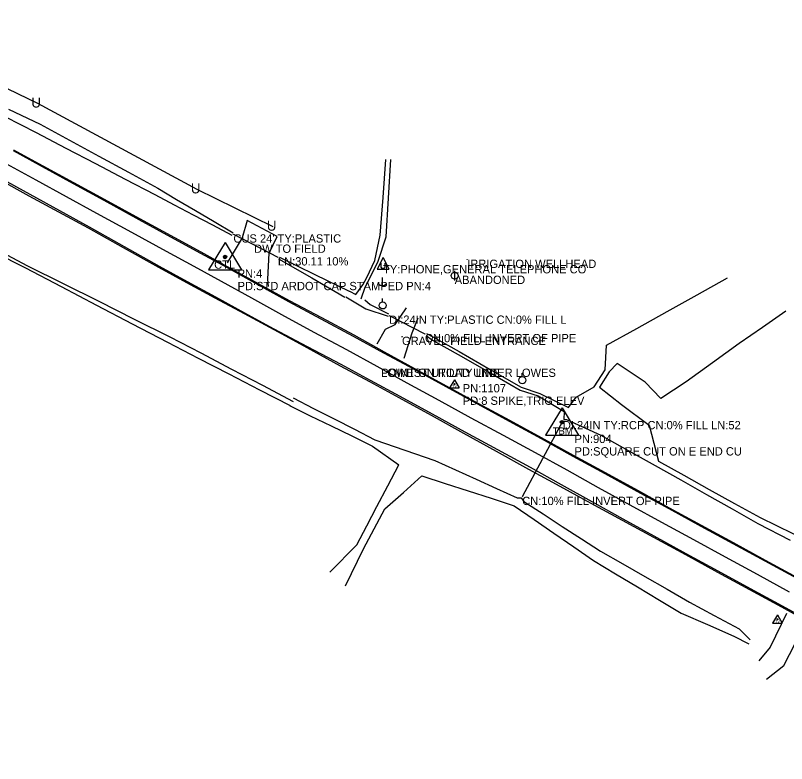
# Model space of a CAD drawing. Extents: x 1411444 to 1458157, y 300965 to 327300.
# Drawn here: x 1455617.6 to 1456081.3, y 301959.3 to 302409.4 of the extents above; entities that cross this region are included whole.
import ezdxf

# ---------------------------------------------------------------- set-up
doc = ezdxf.new("R2010")
doc.units = 0
for name, color, linetype in [('S_CROSS_DRAIN', 7, 'Continuous'), ('S_CROSS_DRAIN_ANNOT', 7, 'Continuous'), ('S_DITCHLINE', 7, 'Continuous'), ('S_DRG_PT_SYM', 7, 'Continuous'), ('S_DRIVEWAY', 7, 'Continuous'), ('S_EDGE_PAVEMENT', 7, 'Continuous'), ('S_ELECTRIC_UTILITIES_ANNOT', 7, 'Continuous'), ('S_MISC_STRUCTURES_ANNOT', 7, 'Continuous'), ('S_MSC_PT_SYM', 7, 'Continuous'), ('S_PAVEMENT_CROWN', 7, 'Continuous'), ('S_PRIMARY_CTL', 7, 'Continuous'), ('S_PRIMARY_CTL_ANNOT', 7, 'Continuous'), ('S_SECONDARY_CTL', 7, 'Continuous'), ('S_SECONDARY_CTL_ANNOT', 7, 'Continuous'), ('S_SHOULDER', 7, 'Continuous'), ('S_SIDE_DRAIN', 7, 'Continuous'), ('S_SIDE_DRAIN_ANNOT', 7, 'Continuous'), ('S_SURVEY_TEXT_ANNOT', 7, 'Continuous'), ('S_UNDERGROUND_CABLE', 7, 'Continuous'), ('S_UTILITY_POLE', 7, 'Continuous'), ('S_UTILITY_POLE_ANNOT', 7, 'Continuous'), ('S_UTL_PT_SYM', 7, 'Continuous')]:
    doc.layers.add(name, color=color, linetype=linetype)

msp = doc.modelspace()

# ---------------------------------------------------------------- linework, layer by layer
at = {"layer": 'S_CROSS_DRAIN'}
for p, q in [((1455748.67, 302277.74), (1455775.41, 302263.98)), ((1455946.75, 302165.41), (1455922.34, 302119.82))]:
    msp.add_line(p, q, dxfattribs=at)
at = {"layer": 'S_DITCHLINE'}
for points in [[(1455613.31, 302353.1), (1455632.46, 302343.94), (1455650.13, 302334.3), (1455667.81, 302324.67), (1455685.48, 302315.03), (1455703.15, 302305.4), (1455714.47, 302298.72), (1455725.79, 302292.05), (1455737.12, 302285.38), (1455748.44, 302278.71)], [(1455611.19, 302348.7), (1455630.11, 302338.98), (1455647.93, 302329.64), (1455665.75, 302320.3), (1455683.57, 302310.96), (1455701.39, 302301.62), (1455712.95, 302295.54), (1455724.51, 302289.45), (1455736.07, 302283.37), (1455747.63, 302277.28)], [(1455822.22, 302241.47), (1455826.43, 302247.25), (1455828.86, 302251.7), (1455833.73, 302262.02), (1455836.98, 302277.13), (1455838.65, 302299.91), (1455840.32, 302322.69)], [(1455825.57, 302238.97), (1455827.89, 302245.84), (1455830.42, 302250.97), (1455835.64, 302261.52), (1455840.6, 302276.21), (1455841.99, 302299.47), (1455843.39, 302322.73)], [(1455604.8, 302266.93), (1455623.63, 302257.6), (1455644.98, 302246.39), (1455666.33, 302235.18), (1455687.68, 302223.96), (1455709.03, 302212.75), (1455727.49, 302203.24), (1455745.95, 302193.73), (1455764.4, 302184.22), (1455782.86, 302174.71)], [(1455606.23, 302268.54), (1455624.82, 302258.77), (1455646.23, 302248.09), (1455667.64, 302237.41), (1455689.05, 302226.72), (1455710.46, 302216.04), (1455729.01, 302206.33), (1455747.56, 302196.61), (1455766.12, 302186.9), (1455784.67, 302177.18)], [(1455775.82, 302263.07), (1455795.76, 302251.46), (1455815.71, 302239.85)], [(1455776.3, 302264.03), (1455797.63, 302253.62), (1455818.28, 302243.54)], [(1455950.15, 302173.46), (1455954.88, 302179.67), (1455965.64, 302185.93), (1455972.18, 302196.15), (1455973, 302210.95), (1455991.2, 302221.08), (1456009.41, 302231.21), (1456027.61, 302241.34), (1456045.82, 302251.46)], [(1455818.38, 302243.51), (1455822.22, 302241.47)], [(1455816.31, 302240.03), (1455828.39, 302232.98), (1455841.69, 302228.51)], [(1455827.76, 302238.3), (1455830.89, 302235.55), (1455842, 302229.89)], [(1456080.85, 302231.48), (1456066.81, 302221.75), (1456052.78, 302212.02), (1456036.82, 302200.48), (1456020.86, 302188.94), (1456005.62, 302178.9), (1455996.36, 302188.75), (1455979.49, 302199.94), (1455974.54, 302195.07), (1455968.85, 302185.66), (1455982.11, 302175.35), (1455998.59, 302162.85), (1456004.29, 302141.21)], [(1455864.67, 302216.87), (1455868.32, 302214.05), (1455883.84, 302205.44), (1455902.44, 302194.74), (1455921.05, 302184.05), (1455931.93, 302180.62), (1455947.6, 302171.05), (1455947.34, 302166.36), (1455949.05, 302166.27), (1455969.67, 302156.8), (1455986.02, 302147.74), (1456002.38, 302138.68), (1456017.8, 302129.95), (1456033.22, 302121.22), (1456048.65, 302112.49), (1456064.07, 302103.76), (1456083.43, 302093.76)], [(1455864.7, 302218.06), (1455868.89, 302215.81), (1455884.5, 302207.22), (1455903.08, 302196.44), (1455921.67, 302185.66), (1455932.91, 302181.95), (1455950.1, 302173.47)], [(1455784.63, 302179.31), (1455796.9, 302173.02), (1455809.17, 302166.72), (1455821.44, 302160.43), (1455833.71, 302154.14), (1455851.72, 302147.93), (1455869.73, 302141.71), (1455882.14, 302136.1), (1455894.55, 302130.49), (1455906.96, 302124.88), (1455919.37, 302119.27), (1455921.7, 302119.11), (1455923.34, 302116.89), (1455934.87, 302109.45), (1455946.39, 302102.01), (1455957.91, 302094.57), (1455969.43, 302087.13), (1455982.8, 302079.46), (1455996.16, 302071.79), (1456009.52, 302064.12), (1456022.88, 302056.45), (1456037.81, 302048.38), (1456052.75, 302040.31), (1456059.49, 302033.64)], [(1455782.34, 302174.69), (1455794.85, 302168.58), (1455807.37, 302162.48), (1455819.88, 302156.38), (1455832.39, 302150.28), (1455848.24, 302139.03)], [(1456004.24, 302141.26), (1456019.52, 302132.77), (1456034.8, 302124.28), (1456050.07, 302115.79), (1456065.35, 302107.3), (1456085.16, 302097.61), (1456104.96, 302087.91), (1456124.76, 302078.22), (1456144.57, 302068.53), (1456162.33, 302059.69), (1456180.09, 302050.85), (1456197.86, 302042.01), (1456215.62, 302033.18), (1456237.44, 302021.54), (1456259.25, 302009.91), (1456281.07, 301998.28), (1456302.88, 301986.64), (1456321.97, 301975.33), (1456341.06, 301964.02), (1456357, 301959.27)], [(1455806.64, 302074.44), (1455822.82, 302090.88), (1455828.88, 302102.41), (1455834.93, 302113.94), (1455841.58, 302126.47), (1455848.23, 302139.01)], [(1455816.03, 302066.14), (1455826.86, 302088.49), (1455833.33, 302100.5), (1455839.79, 302112.52), (1455850.92, 302122.44), (1455862.05, 302132.37)], [(1455862.03, 302132.33), (1455875.91, 302127.85), (1455889.79, 302123.37), (1455903.67, 302118.89), (1455917.55, 302114.41), (1455929.47, 302106.17), (1455941.39, 302097.93), (1455953.31, 302089.69), (1455965.23, 302081.45), (1455978.43, 302073.52), (1455991.63, 302065.58), (1456004.82, 302057.65), (1456018.02, 302049.71), (1456033.82, 302042.87), (1456049.61, 302036.03), (1456058.67, 302031.4)]]:
    msp.add_lwpolyline(points, dxfattribs=at)
at = {"layer": 'S_DRG_PT_SYM'}
for points in [[(1455748.67, 302277.74), (1455748.67, 302277.79), (1455748.67, 302277.74), (1455748.62, 302277.74), (1455748.67, 302277.74), (1455748.67, 302277.69), (1455748.67, 302277.74), (1455748.72, 302277.74)], [(1455775.41, 302263.98), (1455775.41, 302264.03), (1455775.41, 302263.98), (1455775.36, 302263.98), (1455775.41, 302263.98), (1455775.41, 302263.93), (1455775.41, 302263.98), (1455775.46, 302263.98)], [(1455842.3, 302228.87), (1455842.3, 302228.92), (1455842.3, 302228.87), (1455842.25, 302228.87), (1455842.3, 302228.87), (1455842.3, 302228.82), (1455842.3, 302228.87), (1455842.35, 302228.87)], [(1455863.82, 302217.77), (1455863.82, 302217.82), (1455863.82, 302217.77), (1455863.77, 302217.77), (1455863.82, 302217.77), (1455863.82, 302217.72), (1455863.82, 302217.77), (1455863.87, 302217.77)], [(1455946.75, 302165.41), (1455946.75, 302165.46), (1455946.75, 302165.41), (1455946.7, 302165.41), (1455946.75, 302165.41), (1455946.75, 302165.36), (1455946.75, 302165.41), (1455946.8, 302165.41)], [(1455922.34, 302119.82), (1455922.34, 302119.87), (1455922.34, 302119.82), (1455922.29, 302119.82), (1455922.34, 302119.82), (1455922.34, 302119.77), (1455922.34, 302119.82), (1455922.39, 302119.82)]]:
    msp.add_lwpolyline(points, dxfattribs=at)
at = {"layer": 'S_DRIVEWAY'}
for points in [[(1455769.69, 302246.39), (1455769.33, 302250.74), (1455770.17, 302266.43), (1455774.92, 302276.32), (1455756.92, 302285.98), (1455753.97, 302275.69), (1455744.84, 302260.49)], [(1455835.21, 302211.84), (1455840.17, 302220.63), (1455845.87, 302223.56), (1455852.78, 302233.53)], [(1455859.53, 302227.27), (1455855.94, 302218.29), (1455851.21, 302203.01)], [(1456081.28, 302049.64), (1456071.51, 302029.29), (1456064.63, 302021.02)], [(1456069.21, 302009.98), (1456079.73, 302018.24), (1456086.57, 302031.54), (1456101.67, 302034.24)]]:
    msp.add_lwpolyline(points, dxfattribs=at)
at = {"layer": 'S_EDGE_PAVEMENT'}
for points in [[(1455616.19, 302328.12), (1455633.72, 302318.47), (1455652.21, 302308.36), (1455670.71, 302298.26), (1455691.87, 302286.65), (1455713.04, 302275.03), (1455728.95, 302266.41), (1455744.85, 302257.79), (1455763.34, 302247.58), (1455781.83, 302237.37), (1455801.26, 302226.87), (1455820.68, 302216.38), (1455838.98, 302206.48), (1455857.27, 302196.59), (1455876.37, 302186.15), (1455895.47, 302175.71), (1455914.57, 302165.27), (1455933.67, 302154.83), (1455952.88, 302144.29), (1455972.09, 302133.75), (1455991.3, 302123.21), (1456010.51, 302112.67), (1456029.74, 302102.2), (1456048.96, 302091.73), (1456068.18, 302081.25), (1456087.41, 302070.78)], [(1455608.11, 302311.62), (1455626.14, 302301.9), (1455644.02, 302292.07), (1455661.9, 302282.24), (1455682.93, 302270.45), (1455703.95, 302258.66), (1455720.88, 302249.35), (1455737.8, 302240.04), (1455755.4, 302230.45), (1455773, 302220.85), (1455793.1, 302210.18), (1455813.2, 302199.51), (1455830.93, 302189.96), (1455848.65, 302180.41), (1455868.26, 302169.69), (1455887.86, 302158.98), (1455907.46, 302148.26), (1455927.06, 302137.55), (1455945.67, 302127.21), (1455964.28, 302116.88), (1455982.89, 302106.54), (1456001.5, 302096.21), (1456020.78, 302085.71), (1456040.05, 302075.21), (1456059.33, 302064.71), (1456078.61, 302054.21), (1456097.76, 302043.74)]]:
    msp.add_lwpolyline(points, dxfattribs=at)
at = {"layer": 'S_MSC_PT_SYM'}
for points in [[(1455761.09, 302271.59), (1455761.09, 302271.64), (1455761.09, 302271.59), (1455761.04, 302271.59), (1455761.09, 302271.59), (1455761.09, 302271.54), (1455761.09, 302271.59), (1455761.14, 302271.59)], [(1455889.24, 302262.47), (1455889.24, 302262.52), (1455889.24, 302262.47), (1455889.19, 302262.47), (1455889.24, 302262.47), (1455889.24, 302262.42), (1455889.24, 302262.47), (1455889.29, 302262.47)], [(1455850.06, 302216.11), (1455850.06, 302216.16), (1455850.06, 302216.11), (1455850.01, 302216.11), (1455850.06, 302216.11), (1455850.06, 302216.06), (1455850.06, 302216.11), (1455850.11, 302216.11)], [(1455837.47, 302196.93), (1455837.47, 302196.98), (1455837.47, 302196.93), (1455837.42, 302196.93), (1455837.47, 302196.93), (1455837.47, 302196.88), (1455837.47, 302196.93), (1455837.52, 302196.93)]]:
    msp.add_lwpolyline(points, dxfattribs=at)
at = {"layer": 'S_PAVEMENT_CROWN'}
msp.add_lwpolyline([(1455612.22, 302320.13), (1455629.76, 302310.42), (1455648.07, 302300.42), (1455666.38, 302290.42), (1455687.33, 302278.97), (1455708.29, 302267.53), (1455724.83, 302258.58), (1455741.38, 302249.64), (1455759.45, 302239.6), (1455777.52, 302229.56), (1455797.12, 302218.94), (1455816.72, 302208.33), (1455834.84, 302198.32), (1455852.96, 302188.31), (1455872.24, 302177.84), (1455891.52, 302167.38), (1455910.8, 302156.91), (1455930.08, 302146.45), (1455949.08, 302135.97), (1455968.09, 302125.48), (1455987.09, 302115), (1456006.09, 302104.51), (1456025.28, 302094.06), (1456044.46, 302083.61), (1456063.65, 302073.16), (1456082.83, 302062.71)], dxfattribs=at)
at = {"layer": 'S_PRIMARY_CTL'}
for p, q in [((1455743.67, 302272.81), (1455733.63, 302256.29)), ((1455743.67, 302272.81), (1455753.49, 302256.29)), ((1455733.63, 302256.29), (1455753.49, 302256.29)), ((1455946.3, 302173.34), (1455936.26, 302156.83)), ((1455946.3, 302173.34), (1455956.12, 302156.83)), ((1455936.26, 302156.83), (1455956.12, 302156.83))]:
    msp.add_line(p, q, dxfattribs=at)
for centre, radius in [((1455743.67, 302264.11), 1.04), ((1455743.67, 302264.11), 0.609), ((1455743.67, 302264.11), 0.344), ((1455946.3, 302164.64), 1.04), ((1455946.3, 302164.64), 0.609), ((1455946.3, 302164.64), 0.344)]:
    msp.add_circle(centre, radius, dxfattribs=at)
at = {"layer": 'S_SECONDARY_CTL'}
for p, q in [((1455881.56, 302190.23), (1455878.55, 302185.28)), ((1455881.56, 302190.23), (1455884.51, 302185.28)), ((1455878.55, 302185.28), (1455884.51, 302185.28)), ((1456075.81, 302048.71), (1456072.8, 302043.75)), ((1456075.81, 302048.71), (1456078.75, 302043.75)), ((1456072.8, 302043.75), (1456078.75, 302043.75))]:
    msp.add_line(p, q, dxfattribs=at)
for centre, radius in [((1455881.56, 302187.62), 0.311), ((1455881.56, 302187.62), 0.183), ((1455881.56, 302187.62), 0.103), ((1456075.81, 302046.1), 0.311), ((1456075.81, 302046.1), 0.183), ((1456075.81, 302046.1), 0.103)]:
    msp.add_circle(centre, radius, dxfattribs=at)
at = {"layer": 'S_SHOULDER'}
for points in [[(1455616.47, 302328.64), (1455634, 302319.02), (1455652.49, 302308.92), (1455670.98, 302298.83), (1455692.13, 302287.3), (1455713.29, 302275.78), (1455729.13, 302267.1), (1455744.96, 302258.43), (1455763.62, 302248.2), (1455782.29, 302237.97), (1455801.73, 302227.6), (1455821.17, 302217.23), (1455839.37, 302207.09), (1455857.57, 302196.94), (1455876.63, 302186.58), (1455895.69, 302176.22), (1455914.76, 302165.85), (1455933.82, 302155.49), (1455953.07, 302144.93), (1455972.32, 302134.37), (1455991.57, 302123.8), (1456010.81, 302113.24), (1456030.02, 302102.73), (1456049.23, 302092.21), (1456068.45, 302081.7), (1456087.66, 302071.18)], [(1455607.7, 302310.79), (1455625.65, 302300.93), (1455643.52, 302291.24), (1455661.38, 302281.54), (1455682.46, 302269.8), (1455703.54, 302258.05), (1455720.52, 302248.76), (1455737.5, 302239.48), (1455755.19, 302230), (1455772.88, 302220.52), (1455792.83, 302209.57), (1455812.77, 302198.62), (1455830.45, 302189.11), (1455848.13, 302179.6), (1455867.63, 302168.82), (1455887.12, 302158.04), (1455906.62, 302147.26), (1455926.12, 302136.48), (1455944.9, 302126.24), (1455963.69, 302116.01), (1455982.48, 302105.78), (1456001.26, 302095.55), (1456020.53, 302085.04), (1456039.8, 302074.53), (1456059.07, 302064.02), (1456078.33, 302053.51), (1456097.49, 302043.05)]]:
    msp.add_lwpolyline(points, dxfattribs=at)
at = {"layer": 'S_SIDE_DRAIN'}
msp.add_line((1455842.3, 302228.87), (1455863.82, 302217.77), dxfattribs=at)
at = {"layer": 'S_UNDERGROUND_CABLE'}
for p, q in [((1455522.35, 302409.44), (1455630.78, 302356.56)), ((1455630.78, 302356.56), (1455726.69, 302304.9)), ((1455726.69, 302304.9), (1455772.38, 302282.44))]:
    msp.add_line(p, q, dxfattribs=at)
at = {"layer": 'S_UTILITY_POLE'}
for p, q in [((1455838.66, 302263.76), (1455835.13, 302256.67)), ((1455838.66, 302263.76), (1455842.15, 302256.67)), ((1455837.46, 302257.91), (1455837.46, 302260.35)), ((1455838.08, 302257.25), (1455837.46, 302257.91)), ((1455839.28, 302257.25), (1455838.08, 302257.25)), ((1455839.82, 302257.91), (1455839.28, 302257.25)), ((1455839.82, 302260.35), (1455839.82, 302257.91)), ((1455835.13, 302256.67), (1455842.15, 302256.67)), ((1455881.73, 302249.92), (1455881.73, 302255.71)), ((1455838.13, 302251.68), (1455838.13, 302246.95)), ((1455838.33, 302237.09), (1455838.33, 302239.19)), ((1455922.32, 302192.12), (1455922.32, 302194.22))]:
    msp.add_line(p, q, dxfattribs=at)
for centre, radius in [((1455881.73, 302252.85), 2.05), ((1455838.45, 302234.95), 2.13), ((1455922.44, 302189.97), 2.13)]:
    msp.add_circle(centre, radius, dxfattribs=at)
msp.add_arc((1455838.2, 302250.38), 3.41, 226.3972, 313.6028, dxfattribs=at)
at = {"layer": 'S_UTL_PT_SYM'}
msp.add_lwpolyline([(1455837.47, 302196.93), (1455837.47, 302196.98), (1455837.47, 302196.93), (1455837.42, 302196.93), (1455837.47, 302196.93), (1455837.47, 302196.88), (1455837.47, 302196.93), (1455837.52, 302196.93)], dxfattribs=at)

# ---------------------------------------------------------------- texts
at = {"layer": 'S_CROSS_DRAIN_ANNOT'}
for s, p in [("CUS 24' TY:PLASTIC", (1455748.67, 302272.74)), ('LN:30.11 10%', (1455775.41, 302258.98)), ('DI:24IN TY:RCP CN:0% FILL LN:52', (1455946.75, 302160.41)), ('CN:10% FILL INVERT OF PIPE', (1455922.34, 302114.82))]:
    msp.add_text(s, height=5, dxfattribs=at).set_placement(p)
at = {"layer": 'S_ELECTRIC_UTILITIES_ANNOT'}
msp.add_text('LOWEST UTILITY LINE', height=5, dxfattribs=at).set_placement((1455837.47, 302191.93))
at = {"layer": 'S_MISC_STRUCTURES_ANNOT'}
msp.add_text('IRRIGATION WELLHEAD', height=5, dxfattribs=at).set_placement((1455889.24, 302257.47))
at = {"layer": 'S_PRIMARY_CTL'}
for s, height, p in [('CTL', 5, (1455737.08, 302257.03)), ('TBM', 4.287, (1455940.64, 302157.25))]:
    msp.add_text(s, height=height, rotation=360, dxfattribs=at).set_placement(p)
at = {"layer": 'S_PRIMARY_CTL_ANNOT'}
for s, p in [('PN:4', (1455751.17, 302251.61)), ('PD:STD ARDOT CAP STAMPED PN:4', (1455751.17, 302244.11)), ('PN:904', (1455953.8, 302152.14)), ('PD:SQUARE CUT ON E END CU', (1455953.8, 302144.64))]:
    msp.add_text(s, height=5, dxfattribs=at).set_placement(p)
at = {"layer": 'S_SECONDARY_CTL'}
for p in [(1455880.36, 302185.61), (1456074.6, 302044.08)]:
    msp.add_text('TV', height=1.5, rotation=360, dxfattribs=at).set_placement(p)
at = {"layer": 'S_SECONDARY_CTL_ANNOT'}
for s, p in [('PN:1107', (1455886.56, 302182.62)), ('PD:8 SPIKE,TRIG ELEV', (1455886.56, 302175.12))]:
    msp.add_text(s, height=5, dxfattribs=at).set_placement(p)
at = {"layer": 'S_SIDE_DRAIN_ANNOT'}
for s, p in [('DI:24IN TY:PLASTIC CN:0% FILL L', (1455842.3, 302223.87)), ('CN:0% FILL INVERT OF PIPE', (1455863.82, 302212.77))]:
    msp.add_text(s, height=5, dxfattribs=at).set_placement(p)
at = {"layer": 'S_SURVEY_TEXT_ANNOT'}
for s, p in [('DW TO FIELD', (1455761.09, 302266.59)), ('GRAVEL FIELD ENTRANCE', (1455850.06, 302211.11)), ('POINT ON ROAD UNDER LOWES', (1455837.47, 302191.93))]:
    msp.add_text(s, height=5, dxfattribs=at).set_placement(p)
at = {"layer": 'S_UTILITY_POLE_ANNOT'}
for s, p in [('TY:PHONE,GENERAL TELEPHONE CO', (1455838.66, 302254.22)), ('ABANDONED', (1455881.73, 302247.85))]:
    msp.add_text(s, height=5, dxfattribs=at).set_placement(p)
at = {"layer": 'S_UTL_PT_SYM'}
for p in [(1455627.15, 302354.02), (1455723.06, 302302.35), (1455768.75, 302279.9)]:
    msp.add_text('U', height=6, rotation=360, dxfattribs=at).set_placement(p)

doc.saveas('drawing.dxf')
